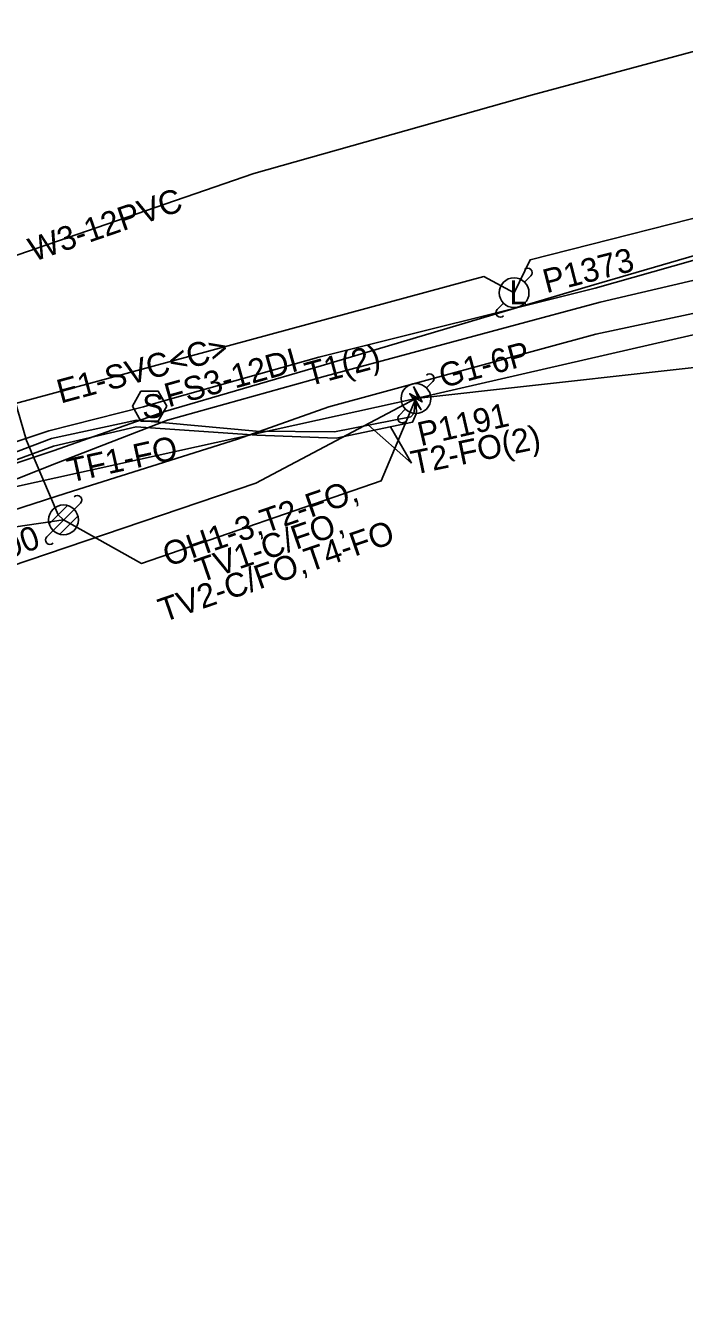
# Model space of a CAD drawing. Extents: x 2336688 to 2352634, y 362473 to 369571.
# Drawn here: x 2351374.5 to 2351485, y 368605.3 to 368818 of the extents above; entities that cross this region are included whole.
import ezdxf

# ---------------------------------------------------------------- set-up
doc = ezdxf.new("R2010")
doc.units = 0
for name, color, linetype in [('RD_EX_DV_Prop', 7, 'Continuous'), ('RD_EX_DV_TX_Prop', 7, 'Continuous'), ('RD_EX_RW', 7, 'Continuous'), ('RD_EX_RW_TX', 7, 'Continuous'), ('RD_HC_CL_Rel', 7, 'Continuous'), ('RD_HC_Data_Tic', 7, 'Continuous'), ('RD_PD_CstnLmt', 7, 'Continuous'), ('RD_PD_Final_TrvlWay', 7, 'Continuous'), ('RD_PD_PatLn2', 7, 'Continuous'), ('RD_PD_PatLn4', 7, 'Continuous'), ('RD_SHT_ShtClip', 7, 'Continuous'), ('RD_Sketch1', 7, 'Continuous'), ('RD_Sketch2', 7, 'Continuous'), ('RD_Sketch5', 7, 'Continuous')]:
    doc.layers.add(name, color=color, linetype=linetype)

msp = doc.modelspace()

# ---------------------------------------------------------------- linework, layer by layer
at = {"layer": 'RD_EX_RW'}
for q in [(2351432.01, 368750.91), (2351435.7, 368750.67)]:
    msp.add_line((2351439.21, 368744.54), q, dxfattribs=at)
at = {"layer": 'RD_EX_RW_TX'}
for points in [[(2351356.36, 368718.44), (2351351.37, 368734.97), (2351351.07, 368736.27), (2351352.08, 368735.83), (2351354.55, 368734.64), (2351363.44, 368738.12), (2351379.73, 368744.54), (2351398.33, 368751.76), (2351424.73, 368759.16), (2351470.85, 368771.57), (2351519.59, 368782.94), (2351559.62, 368792.7), (2351576.11, 368797.45), (2351601.1, 368804.55), (2351618.26, 368808.83), (2351664.35, 368818.5), (2351712.26, 368827.78), (2351760.99, 368838.04), (2351806.87, 368848.05), (2351854.2, 368855.12), (2351907.65, 368859.27)], [(2351224.12, 368690.62), (2351234.5, 368697.35), (2351280.33, 368713.75), (2351311.59, 368722.97), (2351329.76, 368727.3), (2351342.71, 368732.42), (2351349.68, 368736.29), (2351351.07, 368736.27), (2351351.49, 368736.8), (2351351.97, 368737.62), (2351379.15, 368746.62), (2351398.04, 368753.27), (2351424.06, 368760.88), (2351469.79, 368774.45), (2351518.56, 368788.63)], [(2351439.98, 368755.4), (2351440.09, 368752.96), (2351439.42, 368751.44), (2351426.58, 368748.77), (2351413.32, 368749.23), (2351393.05, 368750.66), (2351379.19, 368747.38), (2351340.4, 368733.21), (2351338.54, 368732.83), (2351338.37, 368731.29), (2351340.19, 368726.85), (2351342.99, 368725.87)], [(2351439.98, 368755.4), (2351439.65, 368752.9), (2351439.11, 368752.31), (2351426.3, 368749.79), (2351413.18, 368749.92), (2351393.14, 368751.78), (2351378.88, 368748.66), (2351340.14, 368734.01), (2351338.54, 368732.83)]]:
    msp.add_lwpolyline(points, dxfattribs=at)
at = {"layer": 'RD_HC_CL_Rel'}
msp.add_lwpolyline([(2351006.87, 368605.31), (2351056.9, 368620.23), (2351109.19, 368634.4), (2351152.1, 368649.14), (2351197.21, 368665.27), (2351219.2, 368673.88), (2351241.79, 368682.94), (2351310.92, 368713.38), (2351339.57, 368723.87), (2351370.43, 368735.99), (2351381.33, 368739.5), (2351410.08, 368748.57), (2351425.39, 368754.01), (2351470.14, 368766.16), (2351521.03, 368777.02)], dxfattribs=at)
at = {"layer": 'RD_HC_Data_Tic'}
for p, q in [((2351458.2, 368774.9), (2351459.26, 368775.96)), ((2351453.6, 368770.3), (2351454.66, 368771.37)), ((2351441.74, 368757.17), (2351442.8, 368758.23)), ((2351437.15, 368752.57), (2351438.21, 368753.64)), ((2351382.66, 368736.81), (2351383.72, 368737.87)), ((2351378.48, 368734.4), (2351381.54, 368737.46)), ((2351379.13, 368733.28), (2351382.66, 368736.81)), ((2351380.25, 368732.63), (2351383.31, 368735.69)), ((2351378.07, 368732.22), (2351379.13, 368733.28))]:
    msp.add_line(p, q, dxfattribs=at)
msp.add_lwpolyline([(2351439.58, 368757.41), (2351440.41, 368755.4), (2351438.95, 368756.2), (2351440.83, 368753.52), (2351440.83, 368753.52), (2351439.62, 368755.61), (2351441.01, 368754.81)], close=True, dxfattribs=at)
for centre in [(2351456.43, 368773.13), (2351439.98, 368755.4), (2351380.9, 368735.05)]:
    msp.add_circle(centre, 2.5, dxfattribs=at)
for centre, start, end in [((2351458.73, 368776.49), 315, 135), ((2351454.13, 368769.77), 135, 315), ((2351442.27, 368758.76), 315, 135), ((2351437.68, 368752.04), 135, 315), ((2351383.19, 368738.4), 315, 135), ((2351378.6, 368731.69), 135, 315)]:
    msp.add_arc(centre, 0.75, start, end, dxfattribs=at)
at = {"layer": 'RD_PD_Final_TrvlWay'}
for points in [[(2351380.9, 368735.05), (2351380.01, 368735.9), (2351374.68, 368748.33), (2351371.69, 368758.73), (2351362.67, 368786.92), (2351350.13, 368823.67), (2351348.41, 368830.89), (2351338.9, 368853.84), (2351332.14, 368881.62), (2351334.27, 368886.55), (2351349.44, 368892.24), (2351390.85, 368902), (2351422.65, 368909.4), (2351429.43, 368916.53), (2351427.53, 368923.8)], [(2351962.19, 368868.54), (2351879.61, 368860.3), (2351872.73, 368864.24), (2351807.16, 368856.02), (2351766.5, 368848.48), (2351760.54, 368842.85), (2351755.71, 368847.01), (2351656.05, 368826.47), (2351653.74, 368820.38), (2351649.2, 368824.53), (2351583.65, 368809.05), (2351587.65, 368792.13), (2351587.61, 368789.27), (2351586.29, 368791.8), (2351582.29, 368808.73), (2351542.35, 368799.3), (2351537.51, 368798.37), (2351536.49, 368793.38), (2351533.02, 368797.4), (2351459.1, 368778.67), (2351456.43, 368773.13), (2351451.34, 368775.83), (2351353, 368749.17), (2351345.06, 368741.32)]]:
    msp.add_lwpolyline(points, dxfattribs=at)
at = {"layer": 'RD_SHT_ShtClip'}
for p, q in [((2351439.98, 368755.4), (2351587.61, 368789.27)), ((2351329.41, 368731.07), (2351439.98, 368755.4))]:
    msp.add_line(p, q, dxfattribs=at)
for points in [[(2351439.98, 368755.4), (2351540.29, 368766.59), (2351738.13, 368814.04), (2351832.35, 368849.22)], [(2351069.24, 368629.63), (2351099.2, 368634.72), (2351413.11, 368741.21), (2351439.98, 368755.4)], [(2351380.9, 368735.05), (2351393.99, 368727.75), (2351434.16, 368741.59), (2351439.98, 368755.4)], [(2351201.7, 368675.07), (2351228.45, 368689.67), (2351350.75, 368730.61), (2351380.9, 368735.05)]]:
    msp.add_lwpolyline(points, dxfattribs=at)
at = {"layer": 'RD_Sketch2'}
msp.add_lwpolyline([(2351897.87, 368918.99), (2351839.37, 368906.5), (2351797.47, 368896.96), (2351751.8, 368884.48), (2351707.52, 368870.2), (2351656.24, 368856.32), (2351608.11, 368843.77), (2351558.65, 368832.09), (2351508.67, 368819.53), (2351459.49, 368806.33), (2351412.81, 368793.12), (2351368.32, 368777.82), (2351320.48, 368761.6), (2351291.49, 368752.07), (2351283.21, 368749.13), (2351230.34, 368719.64), (2351184.82, 368699.7), (2351136.28, 368683.67), (2351113.69, 368676.51), (2351093.58, 368668.35), (2351042.86, 368655.18), (2350995.25, 368636.19)], dxfattribs=at)
at = {"layer": 'RD_Sketch5'}
msp.add_lwpolyline([(2350997.52, 368629.24), (2351044.06, 368648.74), (2351094.71, 368664.43), (2351137.99, 368678.97), (2351178.36, 368692), (2351230.47, 368710.98), (2351275.34, 368729.17), (2351305.9, 368740.94), (2351326.85, 368746.53), (2351341.51, 368737.66), (2351378.42, 368749.96), (2351394.31, 368753.99), (2351397.31, 368754.91), (2351423.69, 368762.34), (2351470.05, 368773.88), (2351518.77, 368787.72)], dxfattribs=at)
msp.add_lwpolyline([(2351398.2, 368754.12), (2351396.76, 368756.62), (2351393.87, 368756.62), (2351392.43, 368754.12), (2351393.87, 368751.62), (2351396.76, 368751.62)], close=True, dxfattribs=at)

# ---------------------------------------------------------------- texts
at = {"layer": 'RD_EX_DV_Prop'}
msp.add_text('E1-SVC<C>', height=4, rotation=15.1646, dxfattribs=at).set_placement((2351380.41, 368754.53))
at = {"layer": 'RD_EX_DV_TX_Prop'}
for s, rotation, p in [('P1373', 14.3887, (2351461.86, 368773.03)), ('P1191', 12.9211, (2351440.77, 368747.39)), ('P1190', 19.9486, (2351362.71, 368725.21))]:
    msp.add_text(s, height=4, rotation=rotation, dxfattribs=at).set_placement(p)
at = {"layer": 'RD_EX_RW'}
for s, rotation, p in [('T1(2)', 15.057, (2351422.01, 368757.42)), ('T2-FO(2)', 11.7528, (2351439.62, 368742.59))]:
    msp.add_text(s, height=4, rotation=rotation, dxfattribs=at).set_placement(p)
at = {"layer": 'RD_HC_Data_Tic'}
msp.add_text('L', height=4, rotation=360, dxfattribs=at).set_placement((2351455.62, 368771.2))
at = {"layer": 'RD_PD_CstnLmt'}
msp.add_text('W3-12PVC', height=4, rotation=18.9834, dxfattribs=at).set_placement((2351375.88, 368778.3))
at = {"layer": 'RD_PD_PatLn2'}
msp.add_text('G1-6P', height=4, rotation=15.1938, dxfattribs=at).set_placement((2351444.49, 368757.13))
at = {"layer": 'RD_PD_PatLn4'}
for s, rotation, p in [('TF1-FO', 12.412, (2351382.01, 368741.28)), ('OH1-3,T2-FO,', 19.0131, (2351398.39, 368727.15)), ('TV1-C/FO,', 19.0131, (2351403.84, 368724.5)), ('TV2-C/FO,T4-FO', 19.0131, (2351397.65, 368717.84))]:
    msp.add_text(s, height=4, rotation=rotation, dxfattribs=at).set_placement(p)
at = {"layer": 'RD_Sketch1'}
msp.add_text('FS3-12DI', height=4, rotation=15.7151, dxfattribs=at).set_placement((2351398.48, 368753.9))
at = {"layer": 'RD_Sketch5'}
msp.add_text('S', height=4, dxfattribs=at).set_placement((2351394.09, 368752.12))

doc.saveas('drawing.dxf')
